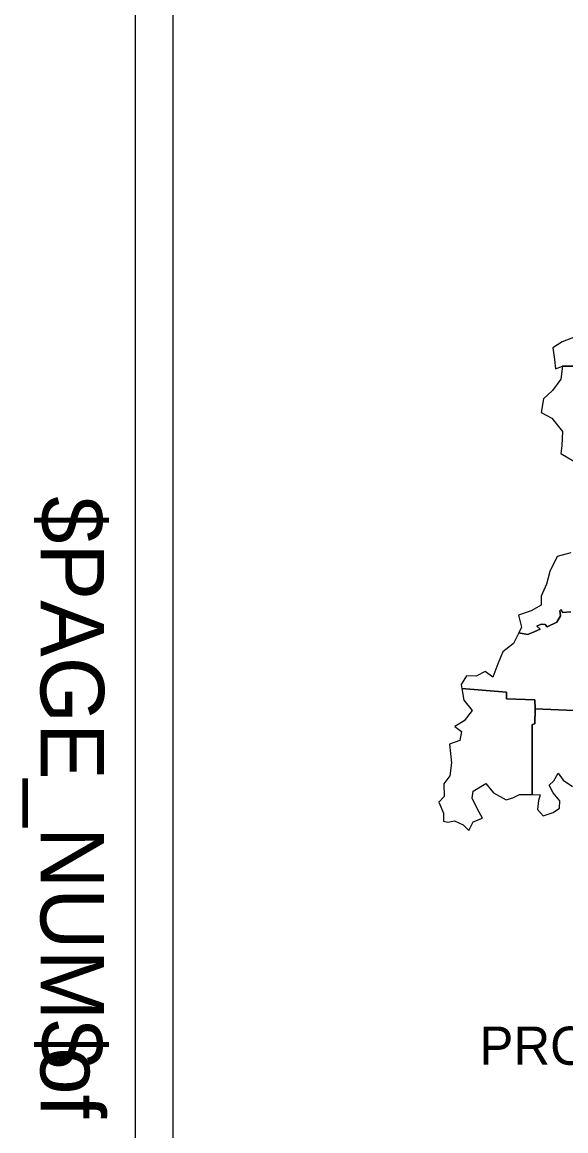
# Model space of a CAD drawing. Extents: x 0.02 to 1.09, y -0.09 to 0.68.
# Drawn here: x 0.0155 to 0.1011, y 0.3512 to 0.5256 of the extents above; entities that cross this region are included whole.
import ezdxf

# ---------------------------------------------------------------- set-up
doc = ezdxf.new("R2010")
doc.units = 0
for name, color, linetype in [('BD_SHT', 7, 'Continuous'), ('BD_SHT_Numbering', 7, 'Continuous'), ('BD_SHT_Text', 7, 'Continuous')]:
    doc.layers.add(name, color=color, linetype=linetype)

msp = doc.modelspace()

# ---------------------------------------------------------------- linework, layer by layer
at = {"layer": 'BD_SHT'}
for p, q in [((0.10046, 0.47531), (0.09899, 0.47435)), ((0.10228, 0.47596), (0.10046, 0.47531)), ((0.09899, 0.47435), (0.09927, 0.47252)), ((0.09927, 0.47252), (0.09943, 0.47105)), ((0.09943, 0.47105), (0.10054, 0.47147)), ((0.10054, 0.47147), (0.10028, 0.46942)), ((0.10255, 0.47145), (0.10041, 0.47142)), ((0.10054, 0.47147), (0.10054, 0.47147)), ((0.10054, 0.47147), (0.1132, 0.47137)), ((0.1132, 0.47137), (0.10054, 0.47147)), ((0.10028, 0.46942), (0.09898, 0.46762)), ((0.09898, 0.46762), (0.09756, 0.46634)), ((0.09756, 0.46634), (0.09719, 0.46416)), ((0.09719, 0.46416), (0.09883, 0.46326)), ((0.09883, 0.46326), (0.10051, 0.46116)), ((0.10051, 0.46116), (0.1004, 0.45898)), ((0.1004, 0.45898), (0.10027, 0.45773)), ((0.10027, 0.45773), (0.1023, 0.45651)), ((0.09971, 0.44149), (0.09856, 0.43918)), ((0.10184, 0.44211), (0.09971, 0.44149)), ((0.09856, 0.43918), (0.09802, 0.43716)), ((0.09802, 0.43716), (0.09718, 0.43529)), ((0.09718, 0.43529), (0.09716, 0.43387)), ((0.0956, 0.43295), (0.09361, 0.43226)), ((0.09716, 0.43387), (0.0956, 0.43295)), ((0.1001, 0.43295), (0.10032, 0.43318)), ((0.10032, 0.43318), (0.1001, 0.43295)), ((0.10019, 0.43218), (0.1001, 0.43295)), ((0.1001, 0.43295), (0.10019, 0.43218)), ((0.10032, 0.43318), (0.10054, 0.43268)), ((0.10054, 0.43268), (0.10032, 0.43318)), ((0.10054, 0.43268), (0.10182, 0.43279)), ((0.10182, 0.43279), (0.10054, 0.43268)), ((0.09361, 0.43226), (0.09407, 0.43037)), ((0.09648, 0.43056), (0.09717, 0.43087)), ((0.09717, 0.43087), (0.09648, 0.43056)), ((0.09717, 0.43087), (0.09781, 0.4308)), ((0.09781, 0.4308), (0.09717, 0.43087)), ((0.0981, 0.43045), (0.09966, 0.43117)), ((0.09966, 0.43117), (0.0981, 0.43045)), ((0.09966, 0.43117), (0.10019, 0.43218)), ((0.10019, 0.43218), (0.09966, 0.43117)), ((0.09365, 0.42951), (0.09282, 0.4278)), ((0.09407, 0.43037), (0.09365, 0.42951)), ((0.09365, 0.42951), (0.095, 0.42923)), ((0.095, 0.42923), (0.09365, 0.42951)), ((0.095, 0.42923), (0.09571, 0.42951)), ((0.09571, 0.42951), (0.095, 0.42923)), ((0.09571, 0.42951), (0.097, 0.43007)), ((0.097, 0.43007), (0.09571, 0.42951)), ((0.097, 0.43007), (0.09648, 0.43056)), ((0.09648, 0.43056), (0.097, 0.43007)), ((0.09781, 0.4308), (0.0981, 0.43045)), ((0.0981, 0.43045), (0.09781, 0.4308)), ((0.09282, 0.4278), (0.09114, 0.42653)), ((0.09114, 0.42653), (0.09034, 0.42465)), ((0.09034, 0.42465), (0.08957, 0.42252)), ((0.0854, 0.42274), (0.08457, 0.42137)), ((0.08697, 0.42269), (0.0854, 0.42274)), ((0.08834, 0.4234), (0.08697, 0.42269)), ((0.08957, 0.42252), (0.08834, 0.4234)), ((0.08457, 0.42137), (0.08468, 0.42074)), ((0.08468, 0.42074), (0.09173, 0.42017)), ((0.09173, 0.42017), (0.08468, 0.42074)), ((0.08468, 0.42074), (0.08502, 0.41891)), ((0.08502, 0.41891), (0.08629, 0.41728)), ((0.09173, 0.42017), (0.0917, 0.4191)), ((0.0917, 0.4191), (0.09173, 0.42017)), ((0.0917, 0.4191), (0.09615, 0.41894)), ((0.09615, 0.41894), (0.0917, 0.4191)), ((0.09615, 0.41894), (0.09622, 0.41757)), ((0.09622, 0.41757), (0.09615, 0.41894)), ((0.08629, 0.41728), (0.08508, 0.41565)), ((0.09619, 0.4152), (0.09622, 0.41757)), ((0.09622, 0.41757), (0.09619, 0.4152)), ((0.09622, 0.41757), (0.10484, 0.41719)), ((0.10484, 0.41719), (0.09622, 0.41757)), ((0.08508, 0.41565), (0.08359, 0.41479)), ((0.09573, 0.41509), (0.09619, 0.4152)), ((0.09619, 0.4152), (0.09573, 0.41509)), ((0.08359, 0.41479), (0.08462, 0.41397)), ((0.08462, 0.41397), (0.08435, 0.41257)), ((0.09575, 0.40408), (0.09573, 0.41509)), ((0.09573, 0.41509), (0.09575, 0.40408)), ((0.08435, 0.41257), (0.08276, 0.412)), ((0.08276, 0.412), (0.08309, 0.40904)), ((0.08309, 0.40904), (0.08282, 0.40703)), ((0.08282, 0.40703), (0.08187, 0.40573)), ((0.09916, 0.40623), (0.09986, 0.40744)), ((0.09986, 0.40744), (0.10065, 0.40634)), ((0.08187, 0.40573), (0.0819, 0.40378)), ((0.08649, 0.4046), (0.08845, 0.40578)), ((0.08845, 0.40578), (0.08965, 0.40434)), ((0.09845, 0.40554), (0.09916, 0.40623)), ((0.09908, 0.40434), (0.09845, 0.40554)), ((0.10065, 0.40634), (0.10208, 0.40533)), ((0.0819, 0.40378), (0.08105, 0.40287)), ((0.08631, 0.40349), (0.08649, 0.4046)), ((0.08718, 0.40175), (0.08631, 0.40349)), ((0.08965, 0.40434), (0.09169, 0.40323)), ((0.09169, 0.40323), (0.09273, 0.40355)), ((0.09273, 0.40355), (0.09376, 0.40408)), ((0.09376, 0.40408), (0.09575, 0.40408)), ((0.09575, 0.40408), (0.09701, 0.404)), ((0.09674, 0.40314), (0.09658, 0.40169)), ((0.09701, 0.404), (0.09674, 0.40314)), ((0.10013, 0.40305), (0.09908, 0.40434)), ((0.10006, 0.40193), (0.10013, 0.40305)), ((0.08105, 0.40287), (0.0818, 0.40115)), ((0.08794, 0.40035), (0.08718, 0.40175)), ((0.09658, 0.40169), (0.09748, 0.40073)), ((0.09748, 0.40073), (0.09907, 0.40125)), ((0.09907, 0.40125), (0.10006, 0.40193)), ((0.0818, 0.40115), (0.08182, 0.39986)), ((0.08182, 0.39986), (0.0825, 0.39971)), ((0.0825, 0.39971), (0.08355, 0.39993)), ((0.08355, 0.39993), (0.0849, 0.3993)), ((0.0858, 0.39842), (0.08649, 0.39977)), ((0.08649, 0.39977), (0.08794, 0.40035)), ((0.0849, 0.3993), (0.0858, 0.39842))]:
    msp.add_line(p, q, dxfattribs=at)
msp.add_lwpolyline([(0.03333, 0.02917), (0.03333, 0.67917), (0.88333, 0.67917), (0.88333, 0.02917)], close=True, dxfattribs=at)
msp.add_lwpolyline([(0.03924, 0.33397), (0.26008, 0.33397), (0.26008, 0.65078), (0.03924, 0.65078), (0.03924, 0.33397)], dxfattribs=at)

# ---------------------------------------------------------------- texts
at = {"layer": 'BD_SHT_Numbering'}
msp.add_text('$PAGE_NUM$', height=0.01, rotation=270, dxfattribs=at).set_placement((0.01841, 0.45101))
at = {"layer": 'BD_SHT_Text'}
msp.add_text('PROJECT LOCATION SHOWN BY', height=0.006, dxfattribs=at).set_placement((0.08745, 0.36155))
msp.add_text('of', height=0.01, rotation=270, dxfattribs=at).set_placement((0.01841, 0.36429))

doc.saveas('drawing.dxf')
